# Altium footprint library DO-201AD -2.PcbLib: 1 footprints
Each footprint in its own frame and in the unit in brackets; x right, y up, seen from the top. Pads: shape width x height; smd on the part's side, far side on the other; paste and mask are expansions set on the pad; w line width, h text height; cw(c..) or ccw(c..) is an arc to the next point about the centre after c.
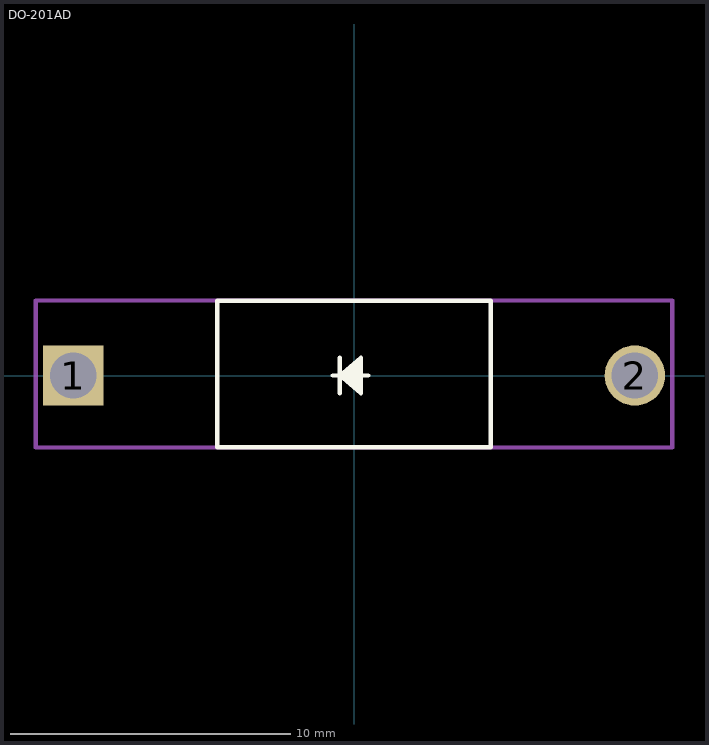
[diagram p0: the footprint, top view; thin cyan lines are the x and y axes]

## DO-201AD [mil]
pads (2):
  rect 85x85 hole 65: 1(-395,0)
  round 85 hole 65: 2(395,0)
Top Overlay:
  lines w6: -30,0 20,0 ; -20,-25 -20,25 ; 10,-20 -20,0 ; 10,-15 -20,0 ; 10,-10 -20,0 ; 10,-5 -20,0 ; 10,5 -20,0 ; 10,10 -20,0 ; 10,15 -20,0 ; 10,20 -20,0 ; -20,0 10,-25 10,25 -20,0 ; -192.5,-100.88 -192.5,105 192.5,105 192.5,-100.88 -192.5,-100.88
Mechanical 15:
  lines w6: -447.5,-101.13 -447.5,105.38 -217.88,105.38 177.12,105.38 447.5,105.38 447.5,-101.13 213.63,-101.13 -181.37,-101.13 -447.5,-101.13
3D body "User Library-MUR440 DO-201AD.step": height 262.2, standoff -78.74, extent -419.65,-104.38 415,104.38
